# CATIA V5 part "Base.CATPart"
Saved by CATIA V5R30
Part number: Base
Bounding box of the stored display mesh (mm): x -30 to 30, y -60 to 60, z -85 to -20
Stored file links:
  D:\PROJECTS\CATIA V56R 2020\Resources\Parts File\c12_catia_v5_6r2020_prt\c12_catia_v5-6r2020 figr_12-35\Base.CATPart
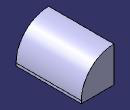
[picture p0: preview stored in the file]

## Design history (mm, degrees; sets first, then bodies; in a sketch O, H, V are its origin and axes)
Body1 (main body)
  Sketch1 on xy-plane, origin (0, 0, 0), H (1, 0, 0), V (0, 1, 0)
    line L1 (30, 60) -> (30, -60)
    line L2 (30, -60) -> (-30, -60)
    line L3 (-30, -60) -> (-30, 60)
    line L4 (-30, 60) -> (30, 60)
    length L2 = 60
    length L3 = 120
    vertical: L1 V, L3 V
    horizontal: L2 H, L4 H
    equidistance: L1 L3 O, L2 L4 O
  Pad1: profile Sketch1, direction (0, 0, -1), length 85, opposite side length -20
  Fillet1: radius 60, on edge [face of Pad1 | face of Pad1]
